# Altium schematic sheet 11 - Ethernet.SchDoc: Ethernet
size A3; PageSetup: Record=PageOptions¦CenterHorizontal=True¦CenterVertical=True¦PrintScale=0.70¦XCorrection=1.00¦YCorrection=1.00¦PrintKind=0¦BorderSize=5000000¦LeftOffset=0¦BottomOffset=0¦Orientation=2¦PaperLength=4200¦PaperWidth=2970¦Scale=100¦PaperSource=7¦PrintQuality=600¦MediaType=1¦DitherType=10¦PaperKind=A4¦PrintScaleMode=1; Author: Juan Anzola; SheetNumber: 11; SheetTotal: 21
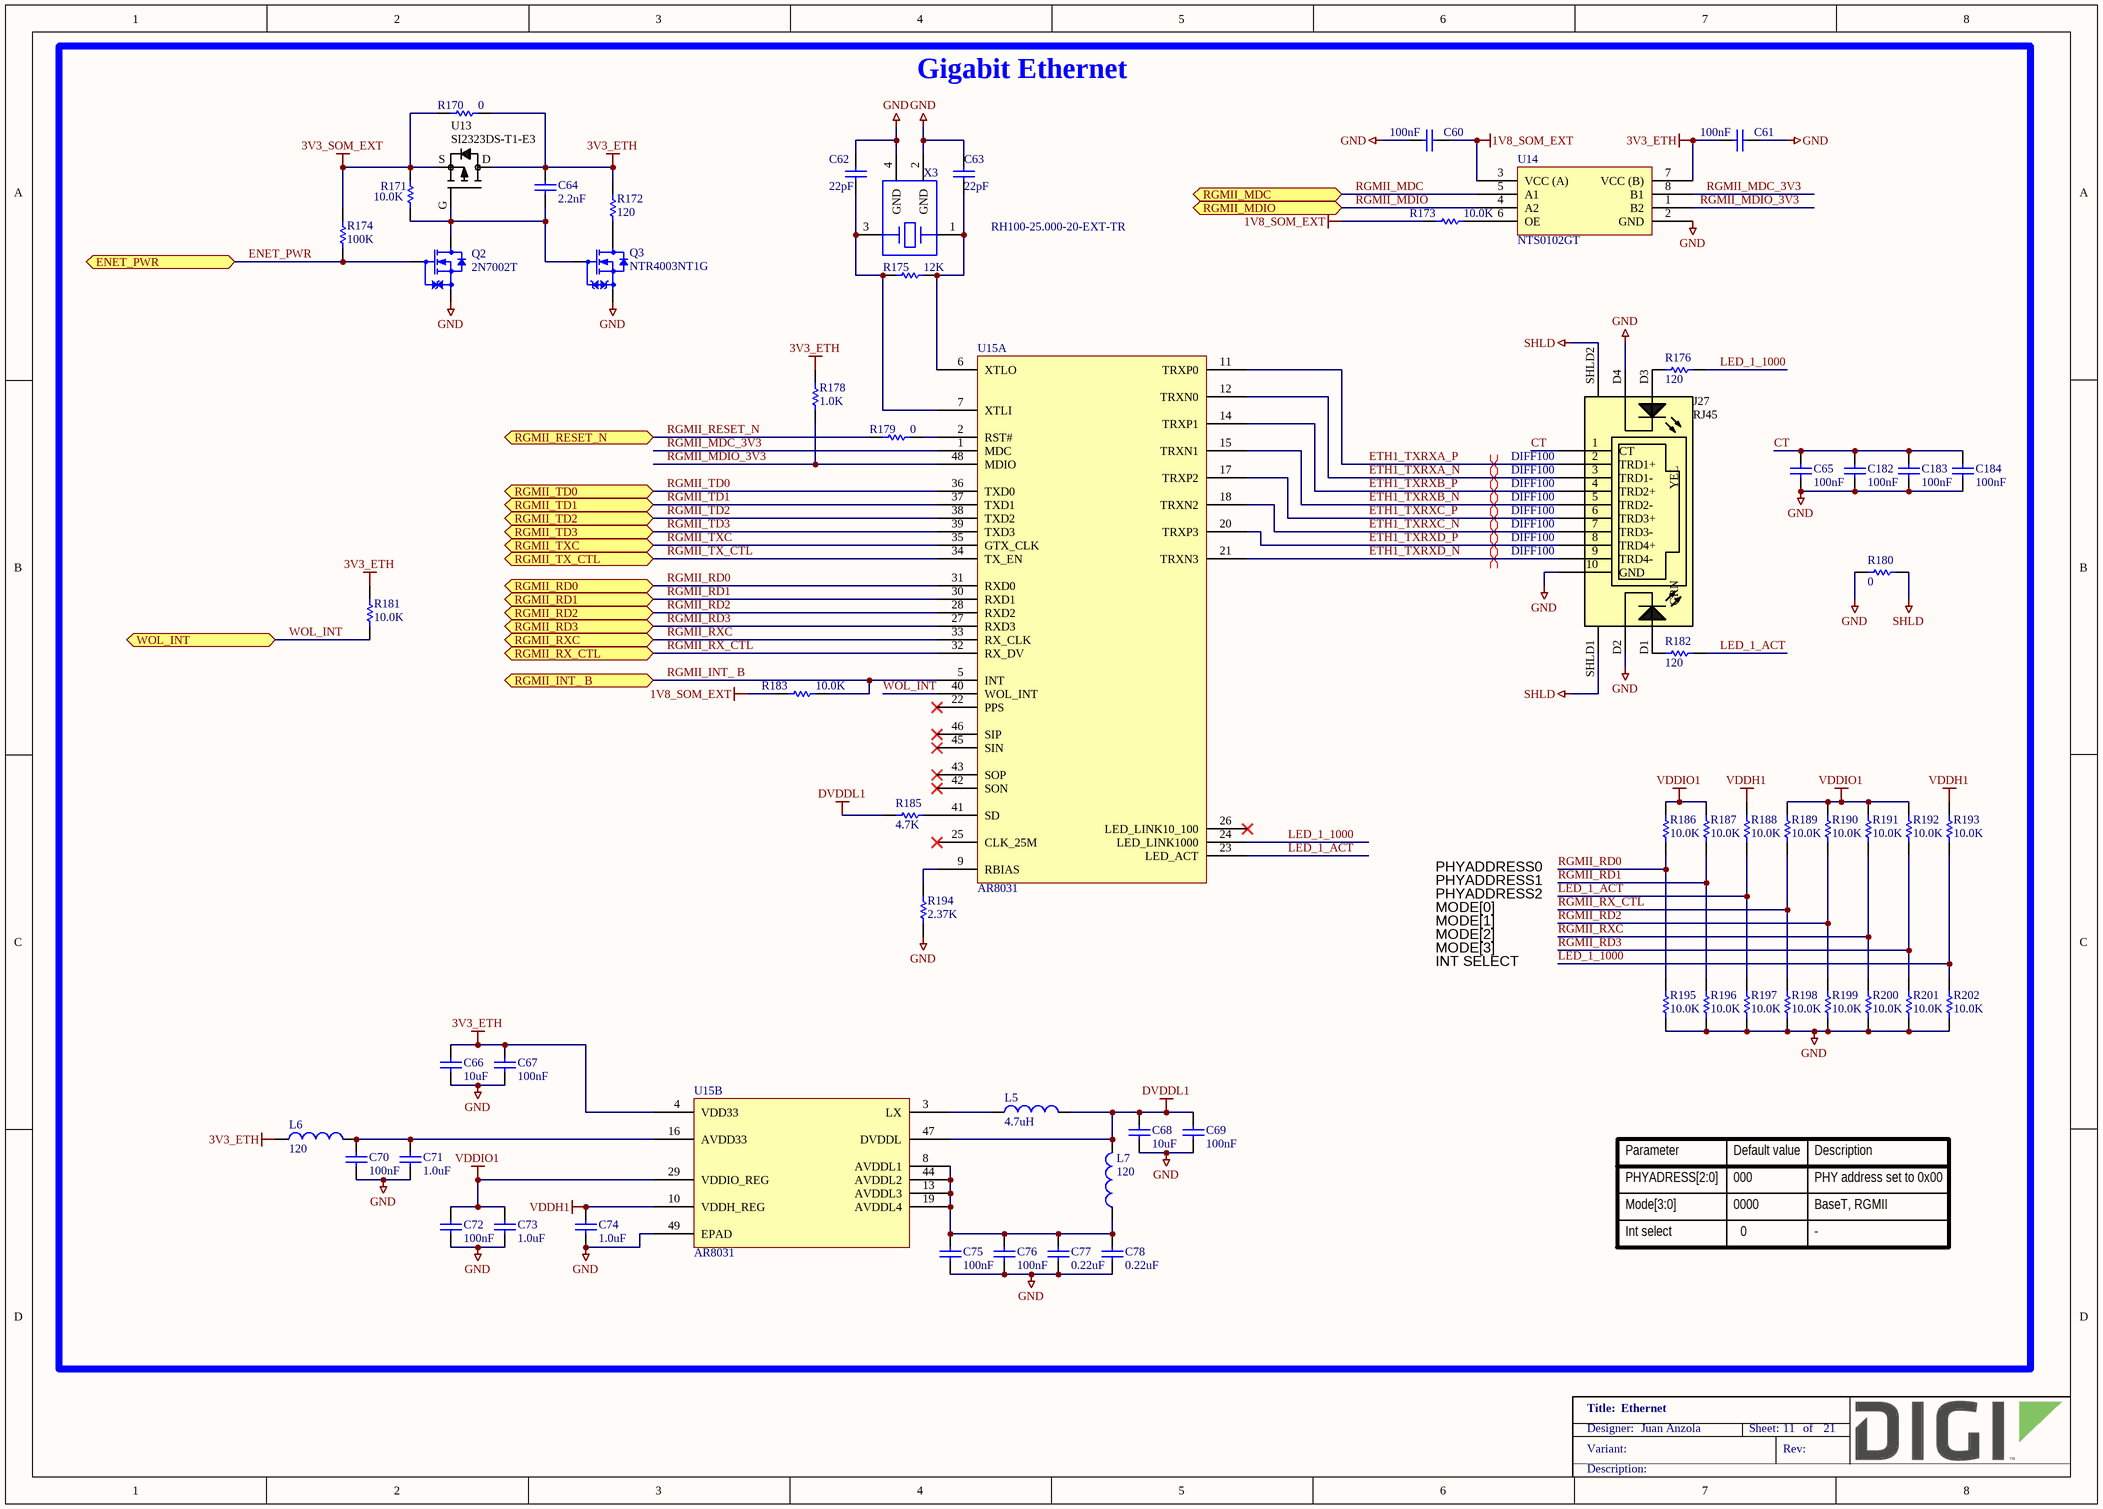
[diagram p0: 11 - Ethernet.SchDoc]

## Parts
C60  100nF  [CAPC1005X55N]
C61  100nF  [CAPC1005X55N]
C62  22pF  [CAPC1005X55N]
C63  22pF  [CAPC1005X55N]
C64  2.2nF  [CAPC1608X90N]
C65  100nF  [CAPC1005X55N]
C66  10uF  [CAPC1005X55N]
C67  100nF  [CAPC1005X55N]
C68  10uF  [CAPC1005X55N]
C69  100nF  [CAPC1005X55N]
C70  100nF  [CAPC1005X55N]
C71  1.0uF  [CAPC1005X55N]
C72  100nF  [CAPC1005X55N]
C73  1.0uF  [CAPC1005X55N]
C74  1.0uF  [CAPC1005X55N]
C75  100nF  [CAPC1005X55N]
C76  100nF  [CAPC1005X55N]
C77  0.22uF  [CAPC1005X55N]
C78  0.22uF  [CAPC1005X55N]
C182  100nF  [CAPC1005X55N]
C183  100nF  [CAPC1005X55N]
C184  100nF  [CAPC1005X55N]
J27  RJ45  [XMULTIPLE_XMG-J1B211]
L5  4.7uH  [INDC2520X100L60N]
L6  120  [INDC1005X60N]
L7  120  [INDC1005X60N]
Q2  2N7002T  [SOTFL50P160X80_GSD-3N]
Q3  NTR4003NT1G  [SOT95P240X110_GSD-3N]
R170  0  [RESC1609X55N]
R171  10.0K  [RESC1005X40N]
R172  120  [RESC1005X40N]
R173  10.0K  [RESC1005X40N]
R174  100K  [RESC1005X40N]
R175  12K  [RESC1609X55N]
R176  120  [RESC1005X40N]
R178  1.0K  [RESC1005X40N]
R179  0  [RESC1005X40N]
R180  0  [RESC3225X60N]
R181  10.0K  [RESC1005X40N]
R182  120  [RESC1005X40N]
R183  10.0K  [RESC1005X40N]
R185  4.7K  [RESC1005X40N]
R186  10.0K  [RESC1005X40N]
R187  10.0K  [RESC1005X40N]
R188  10.0K  [RESC1005X40N]
R189  10.0K  [RESC1005X40N]
R190  10.0K  [RESC1005X40N]
R191  10.0K  [RESC1005X40N]
R192  10.0K  [RESC1005X40N]
R193  10.0K  [RESC1005X40N]
R194  2.37K  [RESC1005X40N]
R195  10.0K  [RESC1005X40N]
R196  10.0K  [RESC1005X40N]
R197  10.0K  [RESC1005X40N]
R198  10.0K  [RESC1005X40N]
R199  10.0K  [RESC1005X40N]
R200  10.0K  [RESC1005X40N]
R201  10.0K  [RESC1005X40N]
R202  10.0K  [RESC1005X40N]
U13  SI2323DS-T1-E3  [SOT95P240X110_GSD-3N]
U14  NTS0102GT  [PSON50P195X100X50-8N]
U15  AR8031  [QFN40P600X600X80-49T380N]  (parts A,B of 2)
X3  RH100-25.000-20-EXT-TR  [OSC210P320X250X90-4N]

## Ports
ENET_PWR (bidir), RGMII_INT_ B (bidir), RGMII_MDC (bidir), RGMII_MDIO (bidir), RGMII_RD0 (bidir), RGMII_RD1 (bidir), RGMII_RD2 (bidir), RGMII_RD3 (bidir), RGMII_RESET_N (bidir), RGMII_RX_CTL (bidir), RGMII_RXC (bidir), RGMII_TD0 (bidir), RGMII_TD1 (bidir), RGMII_TD2 (bidir), RGMII_TD3 (bidir), RGMII_TX_CTL (bidir), RGMII_TXC (bidir), WOL_INT (bidir)

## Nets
1V8_SOM_EXT: C60.2 R173.1 R183.2 U14.3(VCC_(A))
3V3_ETH: C61.2 C64.2 C66.2 C67.2 L6.1 R170.2 R172.1 R178.2 R181.1 U13.D U14.7(VCC_(B)) U15.4(VDD33)
3V3_SOM_EXT: R170.1 R171.1 R174.1 U13.S
DVDDL1: C68.2 C69.2 L5.2 L7.2 R185.1 U15.47(DVDDL)
GND: C60.1 C61.1 C62.1 C63.1 C65.1 C66.1 C67.1 C68.1 C69.1 C70.1 C71.1 C72.1 C73.1 C74.1 C75.1 C76.1 C77.1 C78.1 C182.1 C183.1 C184.1 J27.10(GND) J27.D2 J27.D4 Q2.S Q3.S R180.1 R194.1 R195.1 R196.1 R197.1 R198.1 R199.1 R200.1 R201.1 R202.1 U14.2(GND) U15.49(EPAD) X3.2(GND) X3.4(GND)
SHLD: J27.SHLD1(SHLD) J27.SHLD2(SHLD) R180.2
VDDH1: C74.2 R188.2 R193.2 U15.10(VDDH_REG)
VDDIO1: C72.2 C73.2 R186.2 R187.2 R189.2 R190.2 R191.2 R192.2 U15.29(VDDIO_REG)
CT: C65.2 C182.2 C183.2 C184.2 J27.1(CT)
ENET_PWR: Q2.G R174.2 ; port ENET_PWR
ETH1_TXRXA_N: J27.3(TRD1-) U15.12(TRXN0)
ETH1_TXRXA_P: J27.2(TRD1+) U15.11(TRXP0)
ETH1_TXRXB_N: J27.5(TRD2-) U15.15(TRXN1)
ETH1_TXRXB_P: J27.4(TRD2+) U15.14(TRXP1)
ETH1_TXRXC_N: J27.7(TRD3-) U15.18(TRXN2)
ETH1_TXRXC_P: J27.6(TRD3+) U15.17(TRXP2)
ETH1_TXRXD_N: J27.9(TRD4-) U15.21(TRXN3)
ETH1_TXRXD_P: J27.8(TRD4+) U15.20(TRXP3)
LED_1_1000: R176.1 R193.1 R202.2 U15.24(LED_LINK1000)
LED_1_ACT: R182.1 R188.1 R197.2 U15.23(LED_ACT)
RGMII_INT_ B: R183.1 U15.5(INT) ; port RGMII_INT_ B
RGMII_MDC: U14.5(A1) ; port RGMII_MDC
RGMII_MDC_3V3: U14.8(B1) U15.1(MDC)
RGMII_MDIO: U14.4(A2) ; port RGMII_MDIO
RGMII_MDIO_3V3: R178.1 U14.1(B2) U15.48(MDIO)
RGMII_RD0: R186.1 R195.2 U15.31(RXD0) ; port RGMII_RD0
RGMII_RD1: R187.1 R196.2 U15.30(RXD1) ; port RGMII_RD1
RGMII_RD2: R190.1 R199.2 U15.28(RXD2) ; port RGMII_RD2
RGMII_RD3: R192.1 R201.2 U15.27(RXD3) ; port RGMII_RD3
RGMII_RESET_N: R179.1 ; port RGMII_RESET_N
RGMII_RX_CTL: R189.1 R198.2 U15.32(RX_DV) ; port RGMII_RX_CTL
RGMII_RXC: R191.1 R200.2 U15.33(RX_CLK) ; port RGMII_RXC
RGMII_TD0: U15.36(TXD0) ; port RGMII_TD0
RGMII_TD1: U15.37(TXD1) ; port RGMII_TD1
RGMII_TD2: U15.38(TXD2) ; port RGMII_TD2
RGMII_TD3: U15.39(TXD3) ; port RGMII_TD3
RGMII_TX_CTL: U15.34(TX_EN) ; port RGMII_TX_CTL
RGMII_TXC: U15.35(GTX_CLK) ; port RGMII_TXC
WOL_INT: R181.2 U15.40(WOL_INT) ; port WOL_INT
NetC62_2: C62.2 R175.1 U15.7(XTLI) X3.3
NetC63_2: C63.2 R175.2 U15.6(XTLO) X3.1
NetC64_1: C64.1 Q2.D Q3.G R171.2 U13.G
NetC70_2: C70.2 C71.2 L6.2 U15.16(AVDD33)
NetC75_2: C75.2 C76.2 C77.2 C78.2 L7.1 U15.8(AVDDL1) U15.13(AVDDL3) U15.19(AVDDL4) U15.44(AVDDL2)
NetJ27_D1: J27.D1 R182.2
NetJ27_D3: J27.D3 R176.2
NetL5_1: L5.1 U15.3(LX)
NetQ3_D: Q3.D R172.2
NetR173_2: R173.2 U14.6(OE)
NetR179_2: R179.2 U15.2(RST#)
NetR185_2: R185.2 U15.41(SD)
NetR194_2: R194.2 U15.9(RBIAS)

Not connected (* = marked no-connect by the designer): U15 22(PPS)* 25(CLK_25M)* 26(LED_LINK10_100)* 42(SON)* 43(SOP)* 45(SIN)* 46(SIP)*

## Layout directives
differential pair; net class DIFF100: ETH1_TXRXA_N, ETH1_TXRXA_P, ETH1_TXRXB_N, ETH1_TXRXB_P, ETH1_TXRXC_N, ETH1_TXRXC_P, ETH1_TXRXD_N, ETH1_TXRXD_P

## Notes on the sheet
- Gigabit Ethernet
- PHYADDRESS0
- PHYADDRESS1
- PHYADDRESS2
- MODE[0]
- MODE[1]
- MODE[2]
- MODE[3]
- INT SELECT
- Parameter
- PHYADRESS[2:0]
- Default value
- 000
- Description
- PHY address set to 0x00
- Mode[3:0]
- Int select
- 0000
- 0
- BaseT, RGMII
- -

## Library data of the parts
C60 C61 = 1000006: CAP 100nF 16V 10% X7R 0402; Part_Type: Capacitor; Manufacturer: Murata; Manufacturer_Part_Number: GRM155R71C104KA88D; Component_Life_Cycle_State: CAD Reviewed; Area: 0.95; Project: KITT; Tolerance: 10; Digi_PN: 14050552
C62 C63 = 1001166: CAP CER 22PF 50V 5% NP0 0402; Part_Type: Capacitor; Manufacturer: Murata; Manufacturer_Part_Number: GRM1555C1H220JA01D; Note: 14050749 = Digi No. for GE WDNU; Digi_PN: 14050367; Component_Life_Cycle_State: Reviewed; Area: 0,95; Project: CCWMX6_SBC board; Temp_Coef: C0G, NP0
C64 = 1002727: CAP CER 2200PF 50V X7R 5% 0603; Part_Type: Capacitor; Manufacturer: Kemet; Manufacturer_Part_Number: C0603C222J5RACTU; Digi_PN: 14050443; Component_Life_Cycle_State: Pending; Area: 2,27
C65 C67 C70 C72 C75 C76 C182-C184 = 1000006: CAP 100nF 16V 10% X7R 0402; Part_Type: Capacitor; Manufacturer: Murata; Manufacturer_Part_Number: GRM155R71C104KA88D; Digi_PN: 14050552; Component_Life_Cycle_State: CAD Reviewed; Area: 0,95; Project: KITT; Tolerance: 10
C66 C68 = 1001168: CAP CER 10UF 10V 20% X5R 0402; Part_Type: Capacitor; Manufacturer: Samsung; Manufacturer_Part_Number: CL05A106MP5NUNC; Digi_PN: 14050689; Component_Life_Cycle_State: Reviewed; Area: 0,95; Project: CCWMX6_SBC board
C69 = 1000006: CAP 100nF 16V 10% X7R 0402; Part_Type: Capacitor; Manufacturer: Murata; Manufacturer_Part_Number: GRM155R71C104KA88D; Digi_PN: 14050552; Component_Life_Cycle_State: CAD Reviewed; Area: 0.95; Project: KITT; Tolerance: 10
C71 C73 C74 = 1001167: CAP CER 1UF 10V 10% X5R 0402; Part_Type: Capacitor; Manufacturer: Murata; Manufacturer_Part_Number: GRM155R61A105KE15D; Digi_PN: 14050399; Component_Life_Cycle_State: Reviewed; Area: 0.95; Project: CCWMX6_SBC board
C77 C78 = 1001883: CAP CER 0.22UF 6.3V X7R 0402; Part_Type: Capacitor; Manufacturer: Taiyo Yuden; Manufacturer_Part_Number: JMK105B7224KV-F; Digi_PN: 14000067; Component_Life_Cycle_State: Reviewed; Area: 2.2; Project: Powerley Energy Bridge; Tolerance: 10%
J27 = 1002612: CONN MAGJACK 1PORT 1000 BASE-T IND; Part_Type: Connector; Manufacturer: XMultiple; Manufacturer_Part_Number: XMG-J1B2211NPA-1-DIG; Digi_PN: 18000772; Component_Life_Cycle_State: Created; Area: 339.5; Project: DIGI CC8X SOM
L5 = 1002610: FIXED IND 4.7UH 1.1A 110 MOHM; Manufacturer: Samsung; Manufacturer_Part_Number: CIG22L4R7MNE; Digi_PN: 21000590; Component_Life_Cycle_State: Created; Area: 5; Project: DIGI CC8X SOM; Tolerance: 20%
L6 L7 = 1001175: FERRITE BEAD 120 OHM .35A 0402; Part_Type: Filter; Manufacturer: Wurth Electronics Inc; Manufacturer_Part_Number: 7427927112; Digi_PN: 21000128; Component_Life_Cycle_State: Reviewed; Area: 1,12; Project: CCWMX6_SBC board
Q2 = 1000715: MOSFET N-CH 60V 115MA SOT-523F; Part_Type: Transistor; Manufacturer: Fairchild Semiconductor; Digi_PN: 17050797; Component_Life_Cycle_State: CAD Reviewed; Area: 3.06; Project: SmartMeter2; Note: 17050841 = Digi No. for GE WDNU
Q3 = 1000306: MOSFET N-CH 30V 500MA SOT-23; Part_Type: Transistor; Manufacturer: On Semiconductor; Digi_PN: 17050809; Component_Life_Cycle_State: Proven; Area: 10,92; Project: Adjustable Foundation
R170 = 1000208: RES 0.0 OHM 1/10W 0603; Part_Type: Resistor; Manufacturer: Panasonic - ECG; Manufacturer_Part_Number: ERJ-3GEY0R00V; Note: 13051103 = Digi No. for GE WDNU; Digi_PN: 13050568; Component_Life_Cycle_State: Reviewed; Area: 2.5; Project: Adjustable Foundation; Voltage: 75V
R171 R173 = 1000537: RES 10.0K OHM 1/10W 1% 0402 SMD; Part_Type: Resistor; Manufacturer: Panasonic - ECG; Manufacturer_Part_Number: ERJ-2RKF1002X; Component_Life_Cycle_State: CAD Reviewed; Area: 0.95; Project: KITT; Power_WV_SRF: 100; Digi_PN: 13051084
R172 R176 R182 = 1001158: RES 120 OHM 1/16W 1% 0402 SMD; Part_Type: Resistor; Manufacturer: Yageo; Manufacturer_Part_Number: RC0402FR-07120RL; Digi_PN: 13050832; Component_Life_Cycle_State: Reviewed; Area: 0.95; Project: CCWMX6_SBC board; Note: 13051102 = Digi No. for GE WDNU
R174 = 1000480: RES 100K OHM 1/10W 1% 0402 SMD; Part_Type: Resistor; Manufacturer: Panasonic - ECG; Manufacturer_Part_Number: ERJ-2RKF1003X; Digi_PN: 13051063; Component_Life_Cycle_State: CAD Reviewed; Area: 0.95; Project: KITT; Power_WV_SRF: 100
R175 = 1001200: RES 12.0K OHM 1/10W 1% 0603 SMD; Part_Type: Resistor; Manufacturer: Yageo; Manufacturer_Part_Number: RC0603FR-0712KL; Digi_PN: 13050531; Component_Life_Cycle_State: Reviewed; Area: 2,5; Project: LuCoV2; Power_WV_SRF: 100; Tolerance: 1
R178 = 1000079: RES 1.00K OHM 1/10W 1% 0402 SMD; Part_Type: Resistor; Manufacturer: Panasonic - ECG; Manufacturer_Part_Number: ERJ-2RKF1001X; Digi_PN: 13051085; Component_Life_Cycle_State: Proven; Area: 0,95; Project: Adjustable Foundation; Power_WV_SRF: 10
R179 = 1000076: RES 0.0 OHM 1/10W 0402 SMD; Part_Type: Resistor; Manufacturer: Panasonic - ECG; Manufacturer_Part_Number: ERJ-2GE0R00X; Component_Life_Cycle_State: Proven; Area: 0.95; Project: Adjustable Foundation; Power_WV_SRF: 10; Digi_PN: 13050387
R180 = 1000229: RES 0.0 OHM 1/2W 1210 SMD; Part_Type: Resistor; Manufacturer: Vishay Dale; Manufacturer_Part_Number: CRCW12100000Z0EA; Digi_PN: 13050962; Component_Life_Cycle_State: Proven; Area: 11,07; Project: Adjustable Foundation
R181 R183 R186-R193 R195-R202 = 1000537: RES 10.0K OHM 1/10W 1% 0402 SMD; Part_Type: Resistor; Manufacturer: Panasonic - ECG; Manufacturer_Part_Number: ERJ-2RKF1002X; Digi_PN: 13051084; Component_Life_Cycle_State: CAD Reviewed; Area: 0,95; Project: KITT; Power_WV_SRF: 100
R185 = 1000038: RES 4.7K OHM 1/10W 5% 0402 SMD; Part_Type: Resistor; Manufacturer: Panasonic - ECG; Manufacturer_Part_Number: ERJ-2GEJ472X; Digi_PN: 13050549; Component_Life_Cycle_State: Proven; Area: 0,95; Project: Adjustable Foundation; Power_WV_SRF: 100; Tolerance: 5
R194 = 1000469: RES 2.37K OHM 1/10W 1% 0402 SMD; Part_Type: Resistor; Manufacturer: Panasonic - ECG; Manufacturer_Part_Number: ERJ-2RKF2371X; Component_Life_Cycle_State: Reviewed; Area: 0.95; Project: SDR Prototype RF Board; Power_WV_SRF: 100; Digi_PN: 13000089
U13 = 1001163: MOSFET P-CH 20V 3.7A SOT23-3; Part_Type: IC; Manufacturer: Vishay Siliconix; Digi_PN: 17050358; Component_Life_Cycle_State: Reviewed; Area: 10.92; Project: CCWMX6_SBC board
U14 = 1002597: IC TRANSLATING TXRX 8XSON; Manufacturer: NXP Semiconductors; Manufacturer_Part_Number: NTS0102GT,115; Digi_PN: 16000138; Component_Life_Cycle_State: Created; Area: 3,9; Project: DIGI CC8X SOM
U15 = 1002583: IC TRANSCEIVER ETHERNET 48-QFN; Manufacturer: Qualcomm Atheros, Inc.; Digi_PN: 16000123; Component_Life_Cycle_State: Reviewed; Area: 52.56; Project: DIGI CC8X SOM
X3 = 1001497: SMCRY,25MHZ 50PPM 20PF RH100 EXT; Part_Type: Crystals-Oscillators; Manufacturer: Raltron; Digi_PN: 20000285; Component_Life_Cycle_State: Reviewed; Area: 3,2; Project: CCWMX6_SBC board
